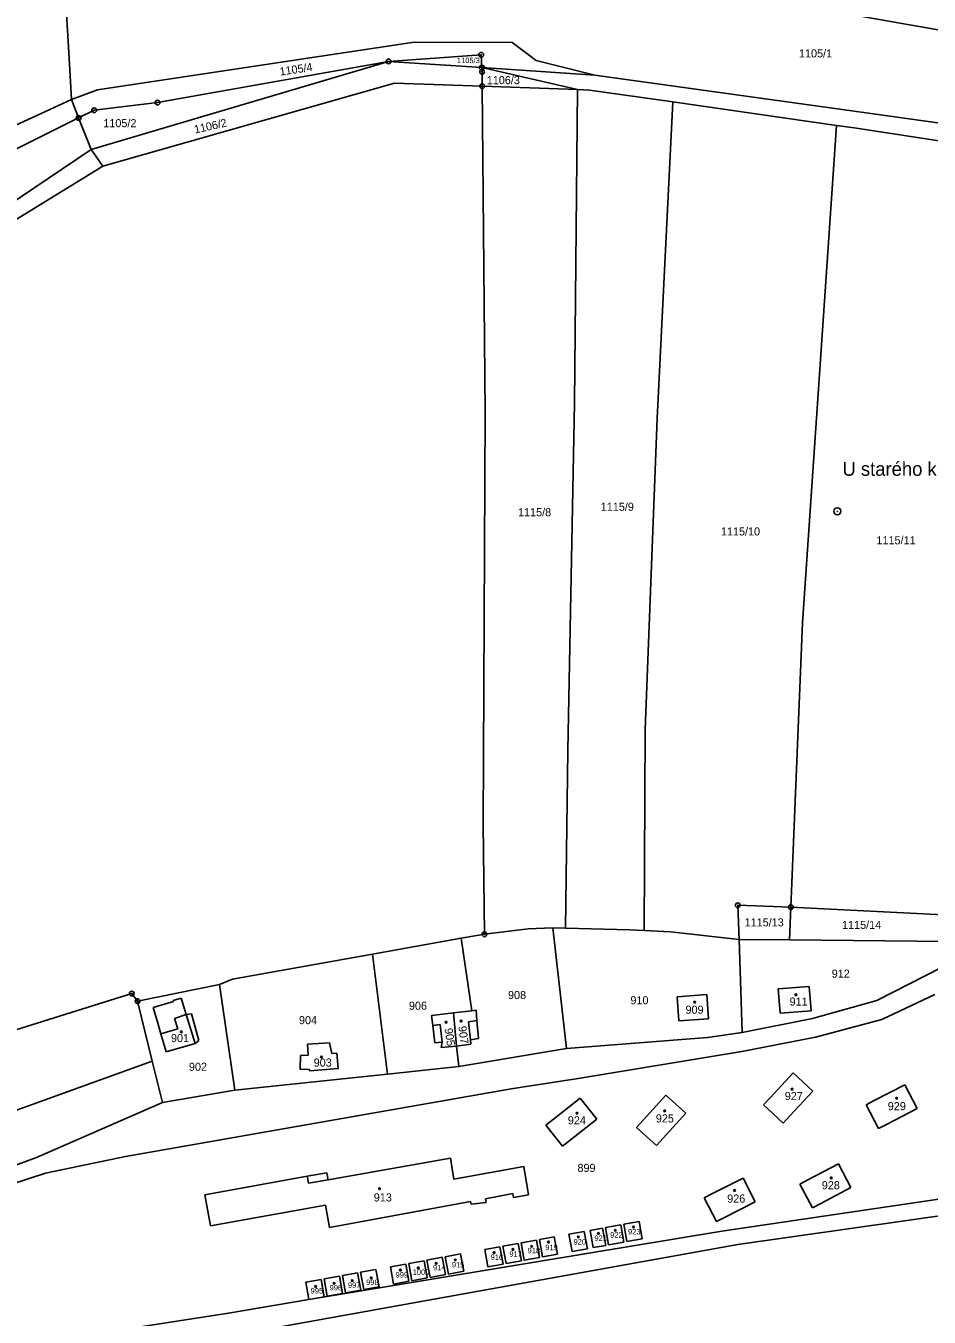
# Model space of a CAD drawing. Extents: x -779596 to -776743, y -1030330 to -1024513.
# Drawn here: x -777976.8 to -777787, y -1026417.6 to -1026146.3 of the extents above; entities that cross this region are included whole.
import ezdxf

# ---------------------------------------------------------------- set-up
doc = ezdxf.new("R2010")
doc.units = 0
for name, color, linetype in [('hranice parcel', 7, 'Continuous'), ('hranice vnitřní', 7, 'Continuous'), ('K_Ú_ hranice', 7, 'Continuous'), ('kultura', 7, 'Continuous'), ('Kód', 7, 'Continuous'), ('názvosloví', 7, 'Continuous'), ('č_pacel stav_', 7, 'Continuous'), ('č_parcel poz_', 7, 'Continuous')]:
    doc.layers.add(name, color=color, linetype=linetype)

msp = doc.modelspace()

# ---------------------------------------------------------------- linework, layer by layer
at = {"layer": 'hranice parcel'}
for points in [[(-777970.07, -1026112.77), (-777967.67, -1026154.31)], [(-777874.32, -1026131.38), (-777756.15, -1026152.26)], [(-777961.75, -1026159.74), (-777895.26, -1026149.69)], [(-777895.26, -1026149.69), (-777874.64, -1026149.75)], [(-777874.64, -1026149.75), (-777869.59, -1026153.6)], [(-777963.11, -1026172.28), (-777900.59, -1026153.77)], [(-777949.14, -1026162.4), (-777900.59, -1026153.77)], [(-777900.59, -1026153.77), (-777881.15, -1026152.37)], [(-777900.59, -1026153.77), (-777881.01, -1026155.06)], [(-777881.15, -1026152.37), (-777881.01, -1026155.06)], [(-777869.59, -1026153.6), (-777857.25, -1026156.62)], [(-777967.67, -1026154.31), (-777967.24, -1026161.77)], [(-777881.01, -1026155.06), (-777880.96, -1026155.97)], [(-777881.01, -1026155.06), (-777857.25, -1026156.62)], [(-777881.01, -1026155.06), (-777860.9, -1026159.68)], [(-777880.96, -1026155.97), (-777880.93, -1026158.96)], [(-777857.25, -1026156.62), (-777802.75, -1026164.22)], [(-777960.61, -1026175.77), (-777899.38, -1026158.3)], [(-777899.38, -1026158.3), (-777880.93, -1026158.96)], [(-777880.93, -1026158.96), (-777860.9, -1026159.68)], [(-777880.93, -1026158.96), (-777880.32, -1026227.56)], [(-777861.54, -1026225.53), (-777860.9, -1026159.68)], [(-777860.9, -1026159.68), (-777858.39, -1026159.77)], [(-777979.04, -1026167.24), (-777967.24, -1026161.77)], [(-777967.24, -1026161.77), (-777961.75, -1026159.74)], [(-777967.24, -1026161.77), (-777965.72, -1026165.63)], [(-777962.46, -1026164.01), (-777949.14, -1026162.4)], [(-777858.39, -1026159.77), (-777840.87, -1026162.28)], [(-777844.19, -1026228.79), (-777840.87, -1026162.28)], [(-777840.87, -1026162.28), (-777806.47, -1026167.2)], [(-777965.72, -1026165.63), (-777962.46, -1026164.01)], [(-777802.75, -1026164.22), (-777694.53, -1026179.37)], [(-777981, -1026173.24), (-777965.72, -1026165.63)], [(-777965.72, -1026165.63), (-777963.11, -1026172.28)], [(-777813.62, -1026271.74), (-777806.47, -1026167.2)], [(-777806.47, -1026167.2), (-777802.77, -1026167.73)], [(-777802.77, -1026167.73), (-777770.79, -1026172.63)], [(-777987.01, -1026188.39), (-777963.11, -1026172.28)], [(-777963.11, -1026172.28), (-777960.61, -1026175.77)], [(-777984.75, -1026190.53), (-777960.61, -1026175.77)], [(-777880.7, -1026314.11), (-777880.32, -1026227.56)], [(-777862.91, -1026298.57), (-777861.54, -1026225.53)], [(-777846.67, -1026294.17), (-777844.19, -1026228.79)], [(-777816.07, -1026331.46), (-777813.62, -1026271.74)], [(-777846.88, -1026336.36), (-777846.67, -1026294.17)], [(-777863.4, -1026335.88), (-777862.91, -1026298.57)], [(-777880.7, -1026314.11), (-777880.47, -1026337.17)], [(-777826.91, -1026338.24), (-777827.23, -1026331.08)], [(-777827.23, -1026331.08), (-777816.07, -1026331.46)], [(-777816.07, -1026331.46), (-777816.35, -1026338.35)], [(-777816.07, -1026331.46), (-777782.67, -1026333.14)], [(-777866.07, -1026335.81), (-777863.19, -1026361.17)], [(-777885.38, -1026338), (-777883.44, -1026350.87)], [(-777826.91, -1026338.24), (-777826.28, -1026357.83)], [(-777904, -1026341.33), (-777900.86, -1026366.56)], [(-777784.42, -1026344.17), (-777798.03, -1026351.06)], [(-777936.15, -1026347.69), (-777932.89, -1026369.93)], [(-777818.73, -1026348.61), (-777812.24, -1026348.17)], [(-777818.3, -1026353.73), (-777818.73, -1026348.61)], [(-777812.24, -1026348.17), (-777811.81, -1026353.25)], [(-777953.34, -1026351.2), (-777950.26, -1026363.81)], [(-777883.44, -1026350.87), (-777883.09, -1026353.23)], [(-777839.98, -1026350.3), (-777833.76, -1026349.84)], [(-777839.61, -1026355.38), (-777839.98, -1026350.3)], [(-777833.76, -1026349.84), (-777833.38, -1026354.92)], [(-777798.03, -1026351.06), (-777811.54, -1026354.85)], [(-777785.81, -1026349.85), (-777796.98, -1026355.07)], [(-777943.15, -1026354), (-777945.56, -1026354.85)], [(-777945.56, -1026354.85), (-777944.91, -1026357.06)], [(-777943.15, -1026354), (-777942.03, -1026353.87)], [(-777942.03, -1026353.87), (-777940.5, -1026359.48)], [(-777886.97, -1026353.67), (-777891.58, -1026354.2)], [(-777891.58, -1026354.2), (-777891.34, -1026356.32)], [(-777883.09, -1026353.23), (-777886.97, -1026353.67)], [(-777886.97, -1026353.67), (-777886.32, -1026360.66)], [(-777883.09, -1026353.23), (-777882.23, -1026353.13)], [(-777882.23, -1026353.13), (-777882.04, -1026355.25)], [(-777833.38, -1026354.92), (-777839.61, -1026355.38)], [(-777811.54, -1026354.85), (-777826.28, -1026357.83)], [(-777811.81, -1026353.25), (-777818.3, -1026353.73)], [(-777796.98, -1026355.07), (-777810.88, -1026358.78)], [(-777944.91, -1026357.06), (-777948.43, -1026358.09)], [(-777891.34, -1026356.32), (-777890.92, -1026360.01)], [(-777882.04, -1026355.25), (-777881.68, -1026359.08)], [(-777947.34, -1026361.85), (-777948.43, -1026358.09)], [(-777941.24, -1026360.12), (-777947.34, -1026361.85)], [(-777940.5, -1026359.48), (-777941.24, -1026360.12)], [(-777917.66, -1026360.23), (-777913.01, -1026359.95)], [(-777917.52, -1026362.57), (-777917.66, -1026360.23)], [(-777913.01, -1026359.95), (-777912.53, -1026362.25)], [(-777890.92, -1026360.01), (-777889.37, -1026359.84)], [(-777889.37, -1026359.84), (-777889.56, -1026360.99)], [(-777883.3, -1026360.25), (-777886.32, -1026360.66)], [(-777881.68, -1026359.08), (-777883.41, -1026359.36)], [(-777883.41, -1026359.36), (-777883.3, -1026360.25)], [(-777833.62, -1026358.85), (-777863.19, -1026361.17)], [(-777826.28, -1026357.83), (-777833.62, -1026358.85)], [(-777810.88, -1026358.78), (-777826.38, -1026361.83)], [(-777919.16, -1026365.53), (-777919.11, -1026362.66)], [(-777919.11, -1026362.66), (-777917.52, -1026362.57)], [(-777912.53, -1026362.25), (-777911.46, -1026362.16)], [(-777911.46, -1026362.16), (-777911.17, -1026365.35)], [(-777889.56, -1026360.99), (-777886.32, -1026360.66)], [(-777886.32, -1026360.66), (-777885.86, -1026364.95)], [(-777863.19, -1026361.17), (-777885.86, -1026364.95)], [(-777826.38, -1026361.83), (-777861.18, -1026367.52)], [(-777950.26, -1026363.81), (-778019.97, -1026388.94)], [(-777950.26, -1026363.81), (-777948.13, -1026372.49)], [(-777917.28, -1026365.59), (-777919.16, -1026365.53)], [(-777917.15, -1026365.89), (-777917.28, -1026365.59)], [(-777911.17, -1026365.35), (-777917.15, -1026365.89)], [(-777885.86, -1026364.95), (-777900.86, -1026366.56)], [(-777920.25, -1026368.6), (-777932.89, -1026369.93)], [(-777900.86, -1026366.56), (-777920.25, -1026368.6)], [(-777861.18, -1026367.52), (-777874.43, -1026369.58)], [(-777820.41, -1026371.53), (-777815.61, -1026366.29)], [(-777815.61, -1026366.29), (-777811.47, -1026370.11)], [(-777874.43, -1026369.58), (-777955.88, -1026383.83)], [(-777932.89, -1026369.93), (-777948.13, -1026372.49)], [(-777847.09, -1026376.26), (-777842.33, -1026370.99)], [(-777842.33, -1026370.99), (-777838.17, -1026374.77)], [(-777811.47, -1026370.11), (-777816.28, -1026375.33)], [(-777798.55, -1026372.12), (-777792.13, -1026368.81)], [(-777792.13, -1026368.81), (-777789.56, -1026373.81)], [(-777974.6, -1026384.05), (-777948.13, -1026372.49)], [(-777865.92, -1026376.04), (-777860.35, -1026371.63)], [(-777860.35, -1026371.63), (-777856.87, -1026376.03)], [(-777821.81, -1026373.02), (-777820.41, -1026371.53)], [(-777817.67, -1026376.84), (-777821.81, -1026373.02)], [(-777800.27, -1026372.99), (-777798.55, -1026372.12)], [(-777797.7, -1026377.99), (-777800.27, -1026372.99)], [(-777789.56, -1026373.81), (-777795.98, -1026377.11)], [(-777867.53, -1026377.3), (-777865.92, -1026376.04)], [(-777856.87, -1026376.03), (-777862.45, -1026380.44)], [(-777848.48, -1026377.77), (-777847.09, -1026376.26)], [(-777838.17, -1026374.77), (-777842.94, -1026380.03)], [(-777816.28, -1026375.33), (-777817.67, -1026376.84)], [(-777864.05, -1026381.7), (-777867.53, -1026377.3)], [(-777844.32, -1026381.54), (-777848.48, -1026377.77)], [(-777795.98, -1026377.11), (-777797.7, -1026377.99)], [(-777862.45, -1026380.44), (-777864.05, -1026381.7)], [(-777842.94, -1026380.03), (-777844.32, -1026381.54)], [(-777987.31, -1026388.76), (-777974.6, -1026384.05)], [(-777955.88, -1026383.83), (-777972.7, -1026387.38)], [(-777887.62, -1026384.2), (-777913.29, -1026388.74)], [(-777886.86, -1026388.64), (-777887.62, -1026384.2)], [(-777972.7, -1026387.38), (-777987.29, -1026392.12)], [(-777913.56, -1026387.27), (-777917.69, -1026388.01)], [(-777913.29, -1026388.74), (-777913.56, -1026387.27)], [(-777872.19, -1026385.99), (-777886.86, -1026388.64)], [(-777871.24, -1026391.89), (-777872.19, -1026385.99)], [(-777812.4, -1026388.71), (-777806.08, -1026385.39)], [(-777806.08, -1026385.39), (-777803.46, -1026390.39)], [(-777917.69, -1026388.01), (-777939.19, -1026391.91)], [(-777832.54, -1026391.66), (-777826.12, -1026388.38)], [(-777826.12, -1026388.38), (-777823.58, -1026393.38)], [(-777814.17, -1026389.64), (-777812.4, -1026388.71)], [(-777811.56, -1026394.63), (-777814.17, -1026389.64)], [(-777939.19, -1026391.91), (-777938.02, -1026398.46)], [(-777880.24, -1026392.73), (-777874.49, -1026391.67)], [(-777880.09, -1026393.52), (-777880.24, -1026392.73)], [(-777874.49, -1026391.67), (-777874.35, -1026392.46)], [(-777874.35, -1026392.46), (-777871.24, -1026391.89)], [(-777834.28, -1026392.54), (-777832.54, -1026391.66)], [(-777831.74, -1026397.53), (-777834.28, -1026392.54)], [(-777781.23, -1026392.29), (-777830.58, -1026399.53)], [(-777803.46, -1026390.39), (-777809.77, -1026393.72)], [(-777938.02, -1026398.46), (-777913.85, -1026394.08)], [(-777913.85, -1026394.08), (-777913.05, -1026398.76)], [(-777913.05, -1026398.76), (-777883.36, -1026393.3)], [(-777883.36, -1026393.3), (-777883.26, -1026393.89)], [(-777883.26, -1026393.89), (-777880.09, -1026393.52)], [(-777823.58, -1026393.38), (-777830, -1026396.65)], [(-777827.21, -1026402.32), (-777780.85, -1026395.77)], [(-777809.77, -1026393.72), (-777811.56, -1026394.63)], [(-777855.03, -1026398.78), (-777851.81, -1026398.2)], [(-777851.81, -1026398.2), (-777851.15, -1026401.83)], [(-777851.19, -1026398.08), (-777847.97, -1026397.49)], [(-777850.53, -1026401.72), (-777851.19, -1026398.08)], [(-777847.97, -1026397.49), (-777847.31, -1026401.13)], [(-777830, -1026396.65), (-777831.74, -1026397.53)], [(-777917.34, -1026413.92), (-777830.58, -1026399.53)], [(-777868.91, -1026401.32), (-777865.79, -1026400.75)], [(-777865.79, -1026400.75), (-777865.12, -1026404.38)], [(-777862.71, -1026400.19), (-777859.49, -1026399.6)], [(-777862.05, -1026403.82), (-777862.71, -1026400.19)], [(-777859.49, -1026399.6), (-777858.83, -1026403.23)], [(-777858.28, -1026399.38), (-777855.65, -1026398.9)], [(-777857.62, -1026403.01), (-777858.28, -1026399.38)], [(-777855.65, -1026398.9), (-777854.99, -1026402.53)], [(-777854.37, -1026402.42), (-777855.03, -1026398.78)], [(-777847.31, -1026401.13), (-777850.53, -1026401.72)], [(-777933.45, -1026421.46), (-777827.21, -1026402.32)], [(-777880.39, -1026403.41), (-777877.21, -1026402.83)], [(-777879.77, -1026407.06), (-777880.39, -1026403.41)], [(-777877.21, -1026402.83), (-777876.54, -1026406.47)], [(-777876.59, -1026402.72), (-777873.37, -1026402.13)], [(-777875.93, -1026406.35), (-777876.59, -1026402.72)], [(-777873.37, -1026402.13), (-777872.7, -1026405.77)], [(-777872.75, -1026402.02), (-777869.53, -1026401.43)], [(-777872.09, -1026405.65), (-777872.75, -1026402.02)], [(-777869.53, -1026401.43), (-777868.86, -1026405.06)], [(-777868.25, -1026404.95), (-777868.91, -1026401.32)], [(-777858.83, -1026403.23), (-777862.05, -1026403.82)], [(-777854.99, -1026402.53), (-777857.62, -1026403.01)], [(-777851.15, -1026401.83), (-777854.37, -1026402.42)], [(-777900.22, -1026407.03), (-777897, -1026406.45)], [(-777896.33, -1026410.08), (-777897, -1026406.45)], [(-777893.16, -1026405.75), (-777896.38, -1026406.33)], [(-777896.38, -1026406.33), (-777895.71, -1026409.97)], [(-777892.49, -1026409.38), (-777893.16, -1026405.75)], [(-777892.54, -1026405.63), (-777889.32, -1026405.04)], [(-777891.87, -1026409.27), (-777892.54, -1026405.63)], [(-777889.32, -1026405.04), (-777888.65, -1026408.68)], [(-777888.7, -1026404.93), (-777885.48, -1026404.34)], [(-777888.03, -1026408.57), (-777888.7, -1026404.93)], [(-777885.48, -1026404.34), (-777884.81, -1026407.98)], [(-777876.54, -1026406.47), (-777879.77, -1026407.06)], [(-777872.7, -1026405.77), (-777875.93, -1026406.35)], [(-777868.86, -1026405.06), (-777872.09, -1026405.65)], [(-777865.12, -1026404.38), (-777868.25, -1026404.95)], [(-777910.94, -1026408.99), (-777914.16, -1026409.58)], [(-777910.28, -1026412.63), (-777910.94, -1026408.99)], [(-777910.32, -1026408.88), (-777907.1, -1026408.29)], [(-777909.66, -1026412.51), (-777910.32, -1026408.88)], [(-777907.1, -1026408.29), (-777906.44, -1026411.93)], [(-777903.26, -1026407.59), (-777906.48, -1026408.18)], [(-777906.48, -1026408.18), (-777905.82, -1026411.81)], [(-777902.6, -1026411.22), (-777903.26, -1026407.59)], [(-777900.22, -1026407.03), (-777899.55, -1026410.67)], [(-777888.65, -1026408.68), (-777891.87, -1026409.27)], [(-777884.81, -1026407.98), (-777888.03, -1026408.57)], [(-777918, -1026410.28), (-777914.78, -1026409.69)], [(-777917.34, -1026413.92), (-777918, -1026410.28)], [(-777914.78, -1026409.69), (-777914.12, -1026413.33)], [(-777914.16, -1026409.58), (-777913.5, -1026413.22)], [(-777906.44, -1026411.93), (-777909.66, -1026412.51)], [(-777905.82, -1026411.81), (-777902.6, -1026411.22)], [(-777899.55, -1026410.67), (-777896.33, -1026410.08)], [(-777895.71, -1026409.97), (-777892.49, -1026409.38)], [(-777934.23, -1026416.77), (-777917.34, -1026413.92)], [(-777914.12, -1026413.33), (-777917.34, -1026413.92)], [(-777913.5, -1026413.22), (-777910.28, -1026412.63)], [(-778000.25, -1026427.03), (-777934.23, -1026416.77)]]:
    msp.add_lwpolyline(points, dxfattribs=at)
at = {"layer": 'hranice vnitřní'}
for points in [[(-777950.04, -1026352.55), (-777945.76, -1026351.31)], [(-777945.83, -1026351.07), (-777944.21, -1026350.6)], [(-777945.76, -1026351.31), (-777945.83, -1026351.07)], [(-777944.21, -1026350.6), (-777943.15, -1026354)], [(-777949.07, -1026355.87), (-777950.04, -1026352.55)], [(-777943.15, -1026354), (-777941.24, -1026360.12)], [(-777948.43, -1026358.09), (-777949.07, -1026355.87)], [(-777891.34, -1026356.32), (-777889.79, -1026356.14)], [(-777889.79, -1026356.14), (-777889.37, -1026359.84)], [(-777882.04, -1026355.25), (-777883.82, -1026355.54)], [(-777883.82, -1026355.54), (-777883.41, -1026359.36)], [(-777917.69, -1026388.01), (-777917.42, -1026389.49)], [(-777917.42, -1026389.49), (-777913.29, -1026388.74)]]:
    msp.add_lwpolyline(points, dxfattribs=at)
at = {"layer": 'K_Ú_ hranice'}
for points in [[(-777880.47, -1026337.17), (-777871.29, -1026335.99)], [(-777871.29, -1026335.99), (-777866.07, -1026335.81)], [(-777866.07, -1026335.81), (-777863.4, -1026335.88)], [(-777863.4, -1026335.88), (-777849.93, -1026336.21)], [(-777904, -1026341.33), (-777885.38, -1026338)], [(-777885.38, -1026338), (-777881.61, -1026337.32)], [(-777881.61, -1026337.32), (-777880.47, -1026337.17)], [(-777849.93, -1026336.21), (-777846.88, -1026336.36)], [(-777846.88, -1026336.36), (-777841.37, -1026336.62)], [(-777841.37, -1026336.62), (-777826.91, -1026338.24)], [(-777826.91, -1026338.24), (-777816.35, -1026338.35)], [(-777816.35, -1026338.35), (-777782.96, -1026338.7)], [(-777933.42, -1026346.6), (-777904, -1026341.33)], [(-777936.15, -1026347.69), (-777933.42, -1026346.6)], [(-778003.56, -1026364.96), (-777954.57, -1026349.63)], [(-777954.57, -1026349.63), (-777953.34, -1026351.2)], [(-777953.34, -1026351.2), (-777936.15, -1026347.69)]]:
    msp.add_lwpolyline(points, dxfattribs=at)
at = {"layer": 'kultura'}
for centre in [(-777836.28, -1026351.43), (-777815.02, -1026349.89), (-777944.16, -1026357.68), (-777888.52, -1026355.65), (-777885.36, -1026355.41), (-777914.7, -1026362.94), (-777815.85, -1026369.71), (-777793.86, -1026371.61), (-777861, -1026374.77), (-777842.58, -1026374.27), (-777807.6, -1026388.35), (-777902.51, -1026390.63), (-777827.91, -1026390.99), (-777860.73, -1026400.79), (-777856.51, -1026400.03), (-777852.96, -1026399.37), (-777849.13, -1026398.69), (-777878.42, -1026404.05), (-777874.49, -1026403.4), (-777870.53, -1026402.73), (-777867.01, -1026401.86), (-777890.59, -1026406.31), (-777886.59, -1026405.61), (-777904.26, -1026409.36), (-777898.1, -1026407.74), (-777894.37, -1026407.27), (-777915.91, -1026411.16), (-777912.04, -1026410.52), (-777908.24, -1026409.94)]:
    msp.add_circle(centre, 0.175, dxfattribs=at)
at = {"layer": 'Kód'}
for centre, radius in [((-777900.59, -1026153.77), 0.5), ((-777900.59, -1026153.77), 0.032), ((-777881.15, -1026152.37), 0.5), ((-777881.15, -1026152.37), 0.032), ((-777881.01, -1026155.06), 0.5), ((-777880.96, -1026155.97), 0.5), ((-777881.01, -1026155.06), 0.032), ((-777880.96, -1026155.97), 0.032), ((-777880.93, -1026158.96), 0.5), ((-777880.93, -1026158.96), 0.032), ((-777949.14, -1026162.4), 0.5), ((-777949.14, -1026162.4), 0.032), ((-777965.72, -1026165.63), 0.5), ((-777962.46, -1026164.01), 0.5), ((-777962.46, -1026164.01), 0.032), ((-777965.72, -1026165.63), 0.032), ((-777806.32, -1026248.29), 0.75), ((-777806.32, -1026248.29), 0.032), ((-777827.23, -1026331.08), 0.5), ((-777827.23, -1026331.08), 0.032), ((-777816.07, -1026331.46), 0.5), ((-777816.07, -1026331.46), 0.032), ((-777880.47, -1026337.17), 0.5), ((-777880.47, -1026337.17), 0.032), ((-777954.57, -1026349.63), 0.5), ((-777954.57, -1026349.63), 0.032), ((-777953.34, -1026351.2), 0.5), ((-777953.34, -1026351.2), 0.032)]:
    msp.add_circle(centre, radius, dxfattribs=at)

# ---------------------------------------------------------------- texts
at = {"layer": 'názvosloví'}
msp.add_text('U starého krchova', height=2.89999, dxfattribs=at).set_placement((-777805.25, -1026240.83))
at = {"layer": 'č_pacel stav_'}
for s, height, p in [('909', 1.7, (-777838.21, -1026353.86)), ('911', 1.7, (-777816.34, -1026352.16)), ('901', 1.7, (-777946.32, -1026359.83)), ('903', 1.7, (-777916.34, -1026364.97)), ('927', 1.7, (-777817.36, -1026372)), ('929', 1.7, (-777795.72, -1026374.13)), ('924', 1.7, (-777862.94, -1026377.1)), ('925', 1.7, (-777844.45, -1026376.71)), ('928', 1.7, (-777809.58, -1026390.75)), ('913', 1.7, (-777903.71, -1026393.31)), ('926', 1.7, (-777829.46, -1026393.55)), ('920', 1.14, (-777861.74, -1026402.36)), ('921', 1.14, (-777857.36, -1026401.6)), ('922', 1.14, (-777854.04, -1026400.9)), ('923', 1.14, (-777850.29, -1026400.24)), ('917', 1.14, (-777875.22, -1026404.9)), ('918', 1.14, (-777871.39, -1026404.2)), ('919', 1.14, (-777867.67, -1026403.55)), ('914', 1.14, (-777891.27, -1026407.79)), ('915', 1.14, (-777887.3, -1026407.17)), ('916', 1.14, (-777879.15, -1026405.58)), ('999', 1.14, (-777899.13, -1026409.29)), ('1000', 1.14, (-777895.54, -1026408.74)), ('995', 1.14, (-777916.97, -1026412.65)), ('996', 1.14, (-777912.99, -1026412)), ('997', 1.14, (-777909.15, -1026411.46)), ('998', 1.14, (-777905.32, -1026410.86))]:
    msp.add_text(s, height=height, dxfattribs=at).set_placement(p)
for s, rotation, p in [('905', 278.70222, (-777888.863, -1026357.007)), ('907', 277.30221, (-777885.957, -1026356.532))]:
    msp.add_text(s, height=1.7, rotation=rotation, dxfattribs=at).set_placement(p)
at = {"layer": 'č_parcel poz_'}
for s, height, p in [('1105/1', 1.7, (-777814.37, -1026152.92)), ('1105/3', 1.14, (-777886.25, -1026154.11)), ('1106/3', 1.7, (-777879.97, -1026158.54)), ('1105/2', 1.7, (-777960.54, -1026167.58)), ('1115/9', 1.7, (-777856.02, -1026248.18)), ('1115/8', 1.7, (-777873.4, -1026249.33)), ('1115/10', 1.7, (-777830.77, -1026253.37)), ('1115/11', 1.7, (-777798.1, -1026255.23)), ('1115/13', 1.7, (-777825.796, -1026335.51)), ('1115/14', 1.7, (-777805.326, -1026336.05)), ('912', 1.7, (-777807.5, -1026346.29)), ('908', 1.7, (-777875.51, -1026350.78)), ('906', 1.7, (-777896.33, -1026353.03)), ('910', 1.7, (-777849.79, -1026351.88)), ('904', 1.7, (-777919.43, -1026356.06)), ('902', 1.7, (-777942.55, -1026365.86)), ('899', 1.7, (-777860.92, -1026387.1))]:
    msp.add_text(s, height=height, dxfattribs=at).set_placement(p)
for s, rotation, p in [('1105/4', 8.40007, (-777923.372, -1026156.753)), ('1106/2', 12.6001, (-777941.249, -1026168.922))]:
    msp.add_text(s, height=1.7, rotation=rotation, dxfattribs=at).set_placement(p)

doc.saveas('drawing.dxf')
